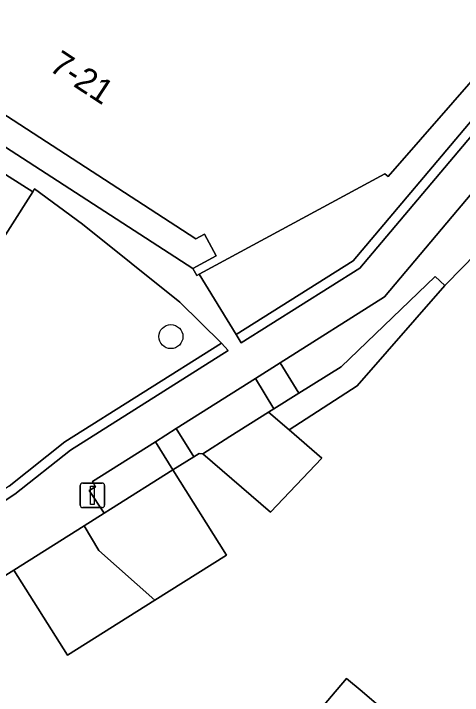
# Model space of a CAD drawing. Extents: x 161798 to 162385, y 382315 to 382833.
# Drawn here: x 162098.63 to 162116.9, y 382631.99 to 382659.78 of the extents above; entities that cross this region are included whole.
import ezdxf

# ---------------------------------------------------------------- set-up
doc = ezdxf.new("R2010")
doc.units = 0
for name, color, linetype in [('IMGEO_Boom', 7, 'Continuous'), ('IMGEO_Erf', 7, 'Continuous'), ('IMGEO_Grasland_overig', 7, 'Continuous'), ('IMGEO_Groenvoorziening', 7, 'Continuous'), ('IMGEO_Haag', 7, 'Continuous'), ('IMGEO_Lichtmast', 7, 'Continuous'), ('IMGEO_Pand', 7, 'Continuous'), ('IMGEO_Pand_nummerreeks', 7, 'Continuous'), ('IMGEO_Parkeervlak_open', 7, 'Continuous'), ('IMGEO_Voetpad_open', 7, 'Continuous')]:
    doc.layers.add(name, color=color, linetype=linetype)

msp = doc.modelspace()

# ---------------------------------------------------------------- linework, layer by layer
at = {"layer": 'IMGEO_Boom'}
msp.add_circle((162105.036, 382646.615), 0.489, dxfattribs=at)
at = {"layer": 'IMGEO_Erf'}
for points in [[(162117.475, 382650.02), (162116.246, 382648.753), (162116.22, 382648.724), (162116.194, 382648.694), (162112.62, 382644.614), (162109.858, 382642.812), (162111.188, 382641.663), (162109.091, 382639.464), (162106.339, 382641.843), (162106.191, 382641.856), (162105.967, 382641.715), (162105.117, 382641.18), (162107.299, 382637.712), (162104.377, 382635.872), (162100.825, 382633.634), (162098.642, 382637.101), (162090.621, 382632.077)], [(162110.35, 382630.522), (162112.187, 382632.685), (162112.822, 382632.146), (162113.31, 382631.732)]]:
    msp.add_lwpolyline(points, dxfattribs=at)
at = {"layer": 'IMGEO_Grasland_overig'}
for points in [[(162107.896, 382646.361), (162112.73, 382649.402), (162123.146, 382661.769), (162122.238, 382662.535), (162122.144, 382662.616), (162121.881, 382662.313), (162122.583, 382661.721), (162112.464, 382649.707), (162107.688, 382646.703)], [(162116.194, 382648.694), (162115.796, 382649.068), (162111.973, 382645.388), (162110.247, 382644.31), (162109.233, 382643.677), (162109.017, 382643.539), (162109.858, 382642.812), (162112.62, 382644.614)], [(162100.721, 382642.321), (162098.453, 382640.526), (162086.912, 382632.968), (162086.587, 382633.461), (162083.617, 382631.522), (162083.938, 382631.006), (162071.632, 382622.978), (162071.854, 382622.645), (162084.484, 382630.885), (162084.164, 382631.401), (162086.472, 382632.908), (162086.798, 382632.415), (162098.687, 382640.201), (162100.953, 382641.994), (162107.365, 382646.048), (162107.093, 382646.349)]]:
    msp.add_lwpolyline(points, close=True, dxfattribs=at)
at = {"layer": 'IMGEO_Groenvoorziening'}
for points in [[(162121.881, 382662.313), (162113.889, 382653.134), (162113.749, 382653.246), (162106.192, 382649.16), (162107.688, 382646.703), (162112.464, 382649.707), (162122.583, 382661.721)], [(162123.491, 382658.338), (162126.268, 382662.17), (162125.705, 382662.471), (162113.737, 382648.232), (162109.486, 382645.543), (162110.247, 382644.31), (162111.973, 382645.388), (162115.796, 382649.068), (162116.194, 382648.694), (162116.22, 382648.724), (162116.246, 382648.753), (162117.475, 382650.02)], [(162109.017, 382643.539), (162109.233, 382643.677), (162108.478, 382644.905), (162105.252, 382642.865), (162105.967, 382641.715), (162106.191, 382641.856), (162106.339, 382641.843), (162107.44, 382642.541)], [(162105.117, 382641.18), (162104.411, 382642.333), (162101.838, 382640.705), (162101.969, 382640.49), (162101.713, 382640.345), (162102.314, 382639.414), (162102.578, 382639.58)]]:
    msp.add_lwpolyline(points, close=True, dxfattribs=at)
msp.add_lwpolyline([(162098.453, 382640.526), (162100.721, 382642.321), (162107.093, 382646.349), (162105.404, 382648.013), (162101.431, 382651.203), (162099.476, 382652.633), (162099.415, 382652.521), (162096.732, 382648.306), (162094.025, 382644.065)], dxfattribs=at)
at = {"layer": 'IMGEO_Haag'}
for points in [[(162123.146, 382661.769), (162122.238, 382662.535), (162122.144, 382662.616), (162121.881, 382662.313), (162122.583, 382661.721), (162112.464, 382649.707), (162107.688, 382646.703), (162107.896, 382646.361), (162112.73, 382649.402)], [(162098.687, 382640.201), (162100.953, 382641.994), (162107.365, 382646.048), (162107.093, 382646.349), (162100.721, 382642.321), (162098.453, 382640.526), (162086.912, 382632.968), (162086.587, 382633.461), (162083.617, 382631.522), (162083.938, 382631.006), (162071.632, 382622.978), (162071.854, 382622.645), (162084.484, 382630.885), (162084.164, 382631.401), (162086.472, 382632.908), (162086.798, 382632.415)]]:
    msp.add_lwpolyline(points, close=True, dxfattribs=at)
at = {"layer": 'IMGEO_Lichtmast'}
for p, q in [((162101.444, 382640.649), (162102.234, 382640.649)), ((162102.234, 382640.649), (162101.444, 382640.649)), ((162101.344, 382639.749), (162101.344, 382640.549)), ((162101.344, 382640.549), (162101.344, 382639.749)), ((162102.334, 382640.549), (162102.334, 382639.749)), ((162102.334, 382639.749), (162102.334, 382640.549)), ((162102.234, 382639.649), (162101.444, 382639.649)), ((162101.444, 382639.649), (162102.234, 382639.649))]:
    msp.add_line(p, q, dxfattribs=at)
msp.add_lwpolyline([(162101.764, 382640.524), (162101.914, 382640.524), (162101.914, 382639.774), (162101.764, 382639.774), (162101.764, 382640.524)], dxfattribs=at)
for centre, start, end in [((162101.444, 382640.549), 90, 180), ((162101.444, 382640.549), 90, 180), ((162102.234, 382640.549), 0, 90), ((162102.234, 382640.549), 360, 90), ((162101.444, 382639.749), 180, 270), ((162101.444, 382639.749), 180, 270), ((162102.234, 382639.749), 270, 0), ((162102.234, 382639.749), 270, 0)]:
    msp.add_arc(centre, 0.1, start, end, dxfattribs=at)
at = {"layer": 'IMGEO_Pand'}
msp.add_lwpolyline([(162094.953, 382661.964), (162092.518, 382659.386), (162106.053, 382650.594), (162106.401, 382650.789), (162106.885, 382649.914), (162105.935, 382649.39), (162106.092, 382649.106), (162106.192, 382649.16), (162113.749, 382653.246), (162113.889, 382653.134), (162121.881, 382662.313)], dxfattribs=at)
for points in [[(162109.858, 382642.812), (162109.017, 382643.539), (162107.44, 382642.541), (162106.339, 382641.843), (162109.091, 382639.464), (162111.188, 382641.663)], [(162105.117, 382641.18), (162102.578, 382639.58), (162102.314, 382639.414), (162101.503, 382638.903), (162102.104, 382637.898), (162104.377, 382635.872), (162107.299, 382637.712)], [(162101.503, 382638.903), (162098.642, 382637.101), (162100.825, 382633.634), (162104.377, 382635.872), (162102.104, 382637.898)], [(162119.612, 382630.456), (162117.627, 382628.119), (162116.502, 382629.075), (162114.819, 382630.45), (162113.31, 382631.732), (162112.822, 382632.146), (162112.187, 382632.685), (162110.35, 382630.522), (162110.985, 382629.982), (162111.512, 382629.534), (162122.235, 382620.427), (162126.084, 382624.959)]]:
    msp.add_lwpolyline(points, close=True, dxfattribs=at)
at = {"layer": 'IMGEO_Parkeervlak_open'}
msp.add_lwpolyline([(162099.415, 382652.521), (162090.982, 382657.86), (162088.266, 382653.675), (162096.732, 382648.306)], close=True, dxfattribs=at)
at = {"layer": 'IMGEO_Voetpad_open'}
for points in [[(162106.885, 382649.914), (162106.401, 382650.789), (162106.053, 382650.594), (162092.518, 382659.386), (162090.218, 382660.88), (162074.142, 382671.323), (162074.251, 382671.491), (162073.412, 382672.036), (162072.703, 382670.936), (162105.935, 382649.39)], [(162109.486, 382645.543), (162108.478, 382644.905), (162109.233, 382643.677), (162110.247, 382644.31)], [(162105.252, 382642.865), (162104.411, 382642.333), (162105.117, 382641.18), (162105.967, 382641.715)]]:
    msp.add_lwpolyline(points, close=True, dxfattribs=at)
for points in [[(162123.146, 382661.769), (162112.73, 382649.402), (162107.896, 382646.361), (162107.688, 382646.703), (162106.192, 382649.16), (162106.092, 382649.106), (162105.935, 382649.39), (162072.703, 382670.936)], [(162090.621, 382632.077), (162098.642, 382637.101), (162101.503, 382638.903), (162102.314, 382639.414), (162101.713, 382640.345), (162101.969, 382640.49), (162101.838, 382640.705), (162104.411, 382642.333), (162105.252, 382642.865), (162108.478, 382644.905), (162109.486, 382645.543), (162113.737, 382648.232), (162125.705, 382662.471)], [(162090.982, 382657.86), (162099.415, 382652.521), (162099.476, 382652.633), (162101.431, 382651.203), (162105.404, 382648.013), (162107.093, 382646.349), (162107.365, 382646.048), (162100.953, 382641.994), (162098.687, 382640.201), (162086.798, 382632.415)]]:
    msp.add_lwpolyline(points, dxfattribs=at)

# ---------------------------------------------------------------- texts
at = {"layer": 'IMGEO_Pand_nummerreeks'}
msp.add_text('7-21', height=1, rotation=326.7799, dxfattribs=at).set_placement((162100.025, 382657.497))

doc.saveas('drawing.dxf')
